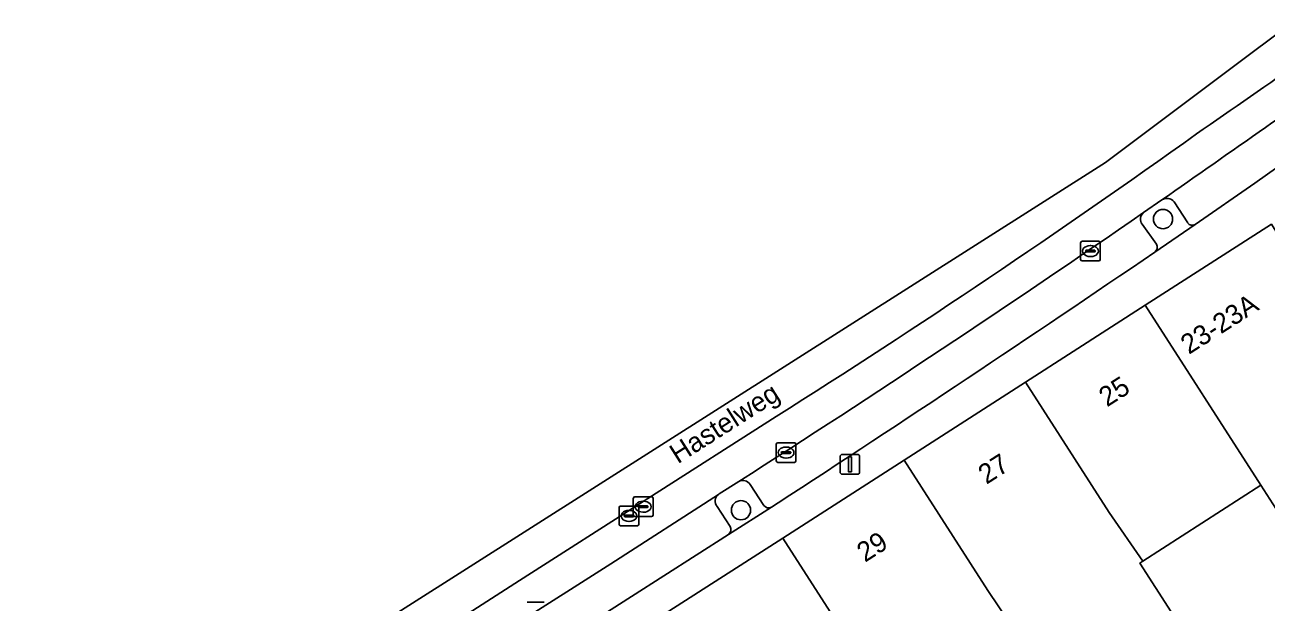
# Model space of a CAD drawing. Extents: x 159499 to 160349, y 382524 to 383273.
# Drawn here: x 159815.5 to 159878.6, y 383182.9 to 383212.2 of the extents above; entities that cross this region are included whole.
import ezdxf

# ---------------------------------------------------------------- set-up
doc = ezdxf.new("R2010")
doc.units = 0
for name, color, linetype in [('IMGEO_Boom', 7, 'Continuous'), ('IMGEO_Erf', 7, 'Continuous'), ('IMGEO_Groenvoorziening', 7, 'Continuous'), ('IMGEO_Kolk', 7, 'Continuous'), ('IMGEO_Lichtmast', 7, 'Continuous'), ('IMGEO_Openbare_ruimte_label', 7, 'Continuous'), ('IMGEO_Pand', 7, 'Continuous'), ('IMGEO_Pand_nummerreeks', 7, 'Continuous'), ('IMGEO_Parkeervlak_open', 7, 'Continuous'), ('IMGEO_Rijbaan_lokaal_gesloten', 7, 'Continuous'), ('IMGEO_Rijbaan_lokaal_open', 7, 'Continuous'), ('IMGEO_Rioolput', 7, 'Continuous'), ('IMGEO_Voetpad_open', 7, 'Continuous')]:
    doc.layers.add(name, color=color, linetype=linetype)

msp = doc.modelspace()

# ---------------------------------------------------------------- linework, layer by layer
at = {"layer": 'IMGEO_Boom'}
for centre in [(159873.328, 383202.336), (159851.874, 383187.529)]:
    msp.add_circle(centre, 0.489, dxfattribs=at)
at = {"layer": 'IMGEO_Erf'}
msp.add_lwpolyline([(159889.273, 383171.719), (159878.306, 383188.801), (159872.295, 383184.937), (159872.151, 383184.845), (159873.746, 383182.365)], dxfattribs=at)
at = {"layer": 'IMGEO_Groenvoorziening'}
for points in [[(159873.268, 383203.309), (159872.34, 383202.665)], [(159874.584, 383202.136), (159873.889, 383203.213)], [(159872.267, 383202.072), (159872.993, 383201.059)], [(159872.909, 383200.654), (159874.962, 383202.059)], [(159851.759, 383188.985), (159850.773, 383188.365), (159850.726, 383188.335)], [(159853.037, 383187.77), (159852.339, 383188.838)], [(159850.662, 383187.724), (159851.326, 383186.7)], [(159851.233, 383186.3), (159853.419, 383187.681)]]:
    msp.add_lwpolyline(points, dxfattribs=at)
for centre, radius, start, end in [((159873.527, 383202.927), 0.462, 38.32839, 124.0961), ((159872.598, 383202.332), 0.421, 127.74414, 218.21993), ((159874.813, 383202.292), 0.277, 214.37111, 302.60123), ((159872.715, 383200.905), 0.318, 307.64179, 28.92334), ((159851.974, 383188.615), 0.428, 31.44346, 120.11246), ((159850.976, 383188), 0.418, 126.71471, 221.32586), ((159853.279, 383187.945), 0.298, 215.7988, 297.97109), ((159851.06, 383186.551), 0.305, 304.55063, 29.27191)]:
    msp.add_arc(centre, radius, start, end, dxfattribs=at)
at = {"layer": 'IMGEO_Kolk'}
for p, q in [((159869.139, 383200.28), (159869.139, 383201.132)), ((159869.214, 383201.206), (159870.066, 383201.206)), ((159870.14, 383201.132), (159870.14, 383200.28)), ((159869.398, 383200.7), (159869.398, 383200.712)), ((159869.836, 383200.663), (159869.438, 383200.663)), ((159869.441, 383200.749), (159869.839, 383200.749)), ((159869.627, 383200.986), (159869.652, 383200.986)), ((159869.882, 383200.712), (159869.882, 383200.7)), ((159870.066, 383200.206), (159869.214, 383200.206)), ((159869.65, 383200.426), (159869.625, 383200.426)), ((159853.667, 383190.036), (159853.667, 383190.888)), ((159853.742, 383190.962), (159854.594, 383190.962)), ((159853.926, 383190.456), (159853.926, 383190.468)), ((159854.364, 383190.419), (159853.966, 383190.419)), ((159853.969, 383190.505), (159854.367, 383190.505)), ((159854.155, 383190.742), (159854.18, 383190.742)), ((159854.41, 383190.468), (159854.41, 383190.456)), ((159854.668, 383190.888), (159854.668, 383190.036)), ((159854.594, 383189.962), (159853.742, 383189.962)), ((159854.178, 383190.182), (159854.153, 383190.182)), ((159841.014, 383182.853), (159841.866, 383182.853))]:
    msp.add_line(p, q, dxfattribs=at)
for points in [[(159869.139, 383200.28), (159869.139, 383201.132)], [(159869.214, 383201.206), (159870.066, 383201.206)], [(159870.14, 383201.132), (159870.14, 383200.28)], [(159870.066, 383200.206), (159869.214, 383200.206)], [(159853.667, 383190.036), (159853.667, 383190.888)], [(159853.742, 383190.962), (159854.594, 383190.962)], [(159854.668, 383190.888), (159854.668, 383190.036)], [(159854.594, 383189.962), (159853.742, 383189.962)], [(159841.014, 383182.853), (159841.866, 383182.853)]]:
    msp.add_lwpolyline(points, dxfattribs=at)
for centre, radius, start, end in [((159869.216, 383201.13), 0.0765, 91.55205, 178.44795), ((159869.216, 383201.13), 0.0765, 91.55205, 178.44795), ((159870.064, 383201.13), 0.0765, 1.55205, 88.44795), ((159870.064, 383201.13), 0.0765, 1.55205, 88.44795), ((159869.438, 383200.709), 0.0403, 85.87752, 175.75265), ((159869.435, 383200.699), 0.0366, 178.93798, 274.71019), ((159869.839, 383200.706), 0.043, 264.86636, 352.45326), ((159869.843, 383200.711), 0.0386, 1.73085, 96.63898), ((159869.216, 383200.282), 0.0765, 181.55205, 268.44795), ((159869.216, 383200.282), 0.0765, 181.55205, 268.44795), ((159870.064, 383200.282), 0.0765, 271.55205, 358.44795), ((159870.064, 383200.282), 0.0765, 271.55205, 358.44795), ((159853.744, 383190.886), 0.0765, 91.55205, 178.44795), ((159853.744, 383190.886), 0.0765, 91.55205, 178.44795), ((159853.966, 383190.465), 0.0403, 85.87752, 175.75265), ((159853.963, 383190.455), 0.0366, 178.93798, 274.71019), ((159854.367, 383190.462), 0.043, 264.86636, 352.45326), ((159854.371, 383190.467), 0.0386, 1.73085, 96.63898), ((159854.592, 383190.886), 0.0765, 1.55205, 88.44795), ((159854.592, 383190.886), 0.0765, 1.55205, 88.44795), ((159853.744, 383190.038), 0.0765, 181.55205, 268.44795), ((159853.744, 383190.038), 0.0765, 181.55205, 268.44795), ((159854.592, 383190.038), 0.0765, 271.55205, 358.44795), ((159854.592, 383190.038), 0.0765, 271.55205, 358.44795)]:
    msp.add_arc(centre, radius, start, end, dxfattribs=at)
for centre, major_axis, ratio, start_param, end_param in [((159869.626, 383200.706), (-0.387, 0.002), 0.722429, 4.712389, 7.853982), ((159869.651, 383200.706), (-0.39, 0.002), 0.717154, 1.570796, 4.712389), ((159854.154, 383190.462), (-0.387, 0.002), 0.722429, 4.712389, 7.853982), ((159854.179, 383190.462), (-0.39, 0.002), 0.717154, 1.570796, 4.712389)]:
    msp.add_ellipse(centre, major_axis=major_axis, ratio=ratio, start_param=start_param, end_param=end_param, dxfattribs=at)
at = {"layer": 'IMGEO_Lichtmast'}
for p, q in [((159856.917, 383189.463), (159856.917, 383190.263)), ((159856.917, 383190.263), (159856.917, 383189.463)), ((159857.017, 383190.363), (159857.807, 383190.363)), ((159857.807, 383190.363), (159857.017, 383190.363)), ((159857.907, 383190.263), (159857.907, 383189.463)), ((159857.907, 383189.463), (159857.907, 383190.263)), ((159857.807, 383189.363), (159857.017, 383189.363)), ((159857.017, 383189.363), (159857.807, 383189.363))]:
    msp.add_line(p, q, dxfattribs=at)
msp.add_lwpolyline([(159857.337, 383190.238), (159857.487, 383190.238), (159857.487, 383189.488), (159857.337, 383189.488), (159857.337, 383190.238)], dxfattribs=at)
for centre, start, end in [((159857.017, 383190.263), 90, 180), ((159857.017, 383190.263), 90, 180), ((159857.807, 383190.263), 0, 90), ((159857.807, 383190.263), 360, 90), ((159857.017, 383189.463), 180, 270), ((159857.017, 383189.463), 180, 270), ((159857.807, 383189.463), 270, 0), ((159857.807, 383189.463), 270, 0)]:
    msp.add_arc(centre, 0.1, start, end, dxfattribs=at)
at = {"layer": 'IMGEO_Pand'}
for points in [[(159883.031, 383195.418), (159881.508, 383197.791), (159878.835, 383202.07), (159872.426, 383197.959), (159878.306, 383188.801), (159889.273, 383171.719), (159894.891, 383175.917), (159890.449, 383182.639), (159887.028, 383180.442), (159880.258, 383190.984), (159884.152, 383193.671)], [(159872.426, 383197.959), (159868.758, 383195.606), (159866.332, 383194.046), (159870.595, 383187.408), (159872.295, 383184.937), (159878.306, 383188.801)], [(159870.595, 383187.408), (159866.332, 383194.046), (159860.163, 383190.081), (159864.424, 383183.446), (159866.095, 383180.951), (159867.81, 383178.389), (159873.746, 383182.365), (159872.151, 383184.845), (159872.295, 383184.937)], [(159860.163, 383190.081), (159853.995, 383186.117), (159859.878, 383176.954), (159866.095, 383180.951), (159864.424, 383183.446)], [(159853.995, 383186.117), (159847.782, 383182.123), (159847.917, 383181.913), (159853.585, 383172.908), (159859.878, 383176.954)]]:
    msp.add_lwpolyline(points, close=True, dxfattribs=at)
at = {"layer": 'IMGEO_Parkeervlak_open'}
for points in [[(159874.962, 383202.059), (159877.994, 383204.159), (159881.505, 383206.647), (159884.369, 383208.682)], [(159873.889, 383203.213), (159874.584, 383202.136)], [(159872.993, 383201.059), (159872.267, 383202.072)], [(159852.339, 383188.838), (159853.037, 383187.77)], [(159850.726, 383188.335), (159845.256, 383184.804), (159835.483, 383178.581), (159829.864, 383174.993)], [(159853.419, 383187.681), (159853.759, 383187.901)], [(159851.326, 383186.7), (159850.662, 383187.724)], [(159831.549, 383173.724), (159836.847, 383177.096), (159846.305, 383183.135), (159851.233, 383186.3)]]:
    msp.add_lwpolyline(points, dxfattribs=at)
for centre, radius, start, end in [((158408.824, 385302.006), 2559.126, 304.906839, 305.194739), ((159873.527, 383202.927), 0.462, 38.32839, 124.0961), ((159471.495, 383783.398), 705.639, 302.608267, 304.61497), ((159872.598, 383202.332), 0.421, 127.74414, 218.21993), ((159874.813, 383202.292), 0.277, 214.37111, 302.60123), ((159260.879, 384098.928), 1086.958, 303.055343, 304.268157), ((159872.715, 383200.905), 0.318, 307.64179, 28.92334), ((159851.974, 383188.615), 0.428, 31.44346, 120.11246), ((159850.976, 383188), 0.418, 126.71471, 221.32586), ((159853.279, 383187.945), 0.298, 215.7988, 297.97109), ((159851.06, 383186.551), 0.305, 304.55063, 29.27191)]:
    msp.add_arc(centre, radius, start, end, dxfattribs=at)
at = {"layer": 'IMGEO_Rijbaan_lokaal_gesloten'}
for points in [[(159872.34, 383202.665), (159873.268, 383203.309)], [(159853.667, 383192.289), (159840.622, 383183.949), (159829.121, 383176.57), (159823.487, 383172.985), (159813.325, 383166.51), (159806.3, 383162.05), (159802.071, 383159.31), (159796.935, 383156.075), (159793.256, 383153.812), (159789.43, 383151.698), (159783.129, 383148.501), (159780.528, 383147.266), (159781.267, 383145.689), (159782.337, 383146.204), (159785.707, 383147.817), (159788.313, 383149.118), (159791.422, 383150.731), (159793.776, 383152.068), (159797.106, 383154.153), (159800.41, 383156.228), (159806.961, 383160.364)], [(159806.961, 383160.364), (159807.939, 383160.989), (159813.8, 383164.72), (159822.635, 383170.351), (159828.873, 383174.384), (159829.864, 383174.993), (159835.483, 383178.581), (159845.256, 383184.804), (159850.726, 383188.335), (159850.773, 383188.365), (159851.759, 383188.985)]]:
    msp.add_lwpolyline(points, dxfattribs=at)
for centre, radius, start, end in [((159609.021, 383592.756), 468.859, 304.5662, 306.19911), ((158408.824, 385302.006), 2559.126, 304.906839, 305.194739), ((159608.717, 383579.413), 458.111, 302.32329, 305.54436), ((159471.495, 383783.398), 705.639, 302.608267, 304.61497)]:
    msp.add_arc(centre, radius, start, end, dxfattribs=at)
at = {"layer": 'IMGEO_Rijbaan_lokaal_open'}
for points in [[(159906.328, 383229.559), (159913.257, 383234.839), (159922.547, 383241.953), (159934.232, 383250.883), (159950.623, 383263.397), (159949.617, 383264.636), (159870.405, 383205.208), (159782.678, 383149.411)], [(159782.678, 383149.411), (159783.129, 383148.501), (159789.43, 383151.698), (159793.256, 383153.812), (159796.935, 383156.075), (159802.071, 383159.31), (159806.3, 383162.05), (159813.325, 383166.51), (159823.487, 383172.985), (159829.121, 383176.57), (159840.622, 383183.949), (159853.667, 383192.289)]]:
    msp.add_lwpolyline(points, dxfattribs=at)
for centre, radius, start, end in [((159609.021, 383592.756), 468.859, 304.5662, 306.19911), ((159608.717, 383579.413), 458.111, 302.32329, 305.54436)]:
    msp.add_arc(centre, radius, start, end, dxfattribs=at)
at = {"layer": 'IMGEO_Rioolput'}
for p, q in [((159846.403, 383187.283), (159846.403, 383188.135)), ((159846.478, 383188.209), (159847.33, 383188.209)), ((159846.891, 383187.989), (159846.916, 383187.989)), ((159847.404, 383188.135), (159847.404, 383187.283)), ((159845.681, 383186.816), (159845.681, 383187.668)), ((159845.756, 383187.742), (159846.608, 383187.742)), ((159845.94, 383187.236), (159845.94, 383187.248)), ((159845.983, 383187.285), (159846.381, 383187.285)), ((159846.169, 383187.522), (159846.194, 383187.522)), ((159846.424, 383187.248), (159846.424, 383187.236)), ((159846.662, 383187.703), (159846.662, 383187.715)), ((159846.682, 383187.668), (159846.682, 383186.816)), ((159847.1, 383187.666), (159846.702, 383187.666)), ((159846.705, 383187.752), (159847.103, 383187.752)), ((159846.914, 383187.429), (159846.889, 383187.429)), ((159847.146, 383187.715), (159847.146, 383187.703)), ((159846.608, 383186.742), (159845.756, 383186.742)), ((159846.378, 383187.199), (159845.98, 383187.199)), ((159846.192, 383186.962), (159846.167, 383186.962)), ((159847.33, 383187.209), (159846.478, 383187.209))]:
    msp.add_line(p, q, dxfattribs=at)
for points in [[(159846.403, 383187.283), (159846.403, 383188.135)], [(159846.478, 383188.209), (159847.33, 383188.209)], [(159847.404, 383188.135), (159847.404, 383187.283)], [(159845.681, 383186.816), (159845.681, 383187.668)], [(159845.756, 383187.742), (159846.608, 383187.742)], [(159846.682, 383187.668), (159846.682, 383186.816)], [(159846.608, 383186.742), (159845.756, 383186.742)], [(159847.33, 383187.209), (159846.478, 383187.209)]]:
    msp.add_lwpolyline(points, dxfattribs=at)
for centre, radius, start, end in [((159846.48, 383188.133), 0.0765, 91.55205, 178.44795), ((159846.48, 383188.133), 0.0765, 91.55205, 178.44795), ((159847.328, 383188.133), 0.0765, 1.55205, 88.44795), ((159847.328, 383188.133), 0.0765, 1.55205, 88.44795), ((159845.758, 383187.666), 0.0765, 91.55205, 178.44795), ((159845.758, 383187.666), 0.0765, 91.55205, 178.44795), ((159845.98, 383187.245), 0.0403, 85.87752, 175.75265), ((159845.977, 383187.235), 0.0366, 178.93798, 274.71019), ((159846.381, 383187.242), 0.043, 264.86636, 352.45326), ((159846.385, 383187.247), 0.0386, 1.73085, 96.63898), ((159846.48, 383187.285), 0.0765, 181.55205, 268.44795), ((159846.48, 383187.285), 0.0765, 181.55205, 268.44795), ((159846.606, 383187.666), 0.0765, 1.55205, 88.44795), ((159846.606, 383187.666), 0.0765, 1.55205, 88.44795), ((159846.702, 383187.712), 0.0403, 85.87752, 175.75265), ((159846.699, 383187.702), 0.0366, 178.93798, 274.71019), ((159847.103, 383187.709), 0.043, 264.86636, 352.45326), ((159847.107, 383187.714), 0.0386, 1.73085, 96.63898), ((159847.328, 383187.285), 0.0765, 271.55205, 358.44795), ((159847.328, 383187.285), 0.0765, 271.55205, 358.44795), ((159845.758, 383186.818), 0.0765, 181.55205, 268.44795), ((159845.758, 383186.818), 0.0765, 181.55205, 268.44795), ((159846.606, 383186.818), 0.0765, 271.55205, 358.44795), ((159846.606, 383186.818), 0.0765, 271.55205, 358.44795)]:
    msp.add_arc(centre, radius, start, end, dxfattribs=at)
for centre, major_axis, ratio, start_param, end_param in [((159846.89, 383187.709), (-0.387, 0.002), 0.722429, 4.712389, 7.853982), ((159846.915, 383187.709), (-0.39, 0.002), 0.717154, 1.570796, 4.712389), ((159846.168, 383187.242), (-0.387, 0.002), 0.722429, 4.712389, 7.853982), ((159846.193, 383187.242), (-0.39, 0.002), 0.717154, 1.570796, 4.712389)]:
    msp.add_ellipse(centre, major_axis=major_axis, ratio=ratio, start_param=start_param, end_param=end_param, dxfattribs=at)
at = {"layer": 'IMGEO_Voetpad_open'}
for points in [[(159884.369, 383208.682), (159881.505, 383206.647), (159877.994, 383204.159), (159874.962, 383202.059), (159872.909, 383200.654)], [(159828.505, 383169.737), (159828.738, 383169.887), (159834.587, 383173.647), (159840.668, 383177.557), (159846.963, 383181.604), (159847.782, 383182.123), (159853.995, 383186.117), (159860.163, 383190.081), (159866.332, 383194.046), (159868.758, 383195.606), (159872.426, 383197.959), (159878.835, 383202.07)], [(159853.759, 383187.901), (159853.419, 383187.681), (159851.233, 383186.3), (159846.305, 383183.135), (159836.847, 383177.096), (159831.549, 383173.724), (159829.345, 383172.324), (159821.969, 383167.609), (159809.636, 383159.722), (159807.433, 383158.312), (159801.745, 383154.701), (159796.426, 383151.401), (159793.075, 383149.316)]]:
    msp.add_lwpolyline(points, dxfattribs=at)
msp.add_arc((159260.879, 384098.928), 1086.958, 303.055343, 304.268157, dxfattribs=at)

# ---------------------------------------------------------------- texts
at = {"layer": 'IMGEO_Openbare_ruimte_label'}
msp.add_text('Hastelweg', height=1, rotation=32.4668, dxfattribs=at).set_placement((159848.665, 383189.863))
at = {"layer": 'IMGEO_Pand_nummerreeks'}
for s, p in [('23-23A', (159874.642, 383195.426)), ('25', (159870.483, 383192.756)), ('27', (159864.351, 383188.818)), ('29', (159858.18, 383184.856))]:
    msp.add_text(s, height=1, rotation=32.70443, dxfattribs=at).set_placement(p)

doc.saveas('drawing.dxf')
